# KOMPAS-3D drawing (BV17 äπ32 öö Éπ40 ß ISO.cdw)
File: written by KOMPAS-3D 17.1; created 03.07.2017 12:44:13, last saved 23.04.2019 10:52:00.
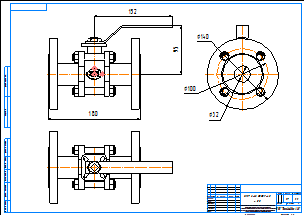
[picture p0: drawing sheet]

Sheet 1: A2, landscape

Title block, sheet 1: name: BV17 Ду32 ФФ Ру40 / с ISO; material: Внимание! Данный продукт является объектом авторского права ООО «Торговый Дом АДЛ». / Запрещается изменение, копирование, распространение / (в том числе путем копирования на другие сайты и ресурсы в Интернете) / или любое иное использование информации и объектов без предварительного / согласия правообладателя (ООО «Торговый Дом АДЛ»).; mass: 1,7; sheets: 1; organisation: ООО "Торговый дом АДЛ"; sheet format: A2; stored path: C:\Users\kka\KOMPAS_Work\!Trash\СС02 СС03 ФФ Смотровые стекла\СС01.cdw

Views: Спереди 1, Проекционный вид 2, Проекционный вид 3
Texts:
  Klimkovich
  ADL
Dimensions and other numbers on the sheet: 180; 152; 95; 100; 140; 32; 1:1; 1; 1,7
